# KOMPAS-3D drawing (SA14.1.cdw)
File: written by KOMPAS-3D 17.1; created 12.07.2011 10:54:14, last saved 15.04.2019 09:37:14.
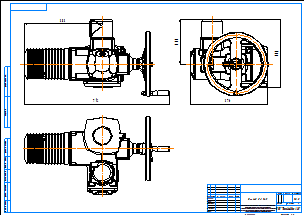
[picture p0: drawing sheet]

Title block, sheet 1: name: Привод SA 14.1; material: Внимание! Данный продукт является объектом авторского права ООО «Торговый Дом АДЛ». / Запрещается изменение, копирование, распространение / (в том числе путем копирования на другие сайты и ресурсы в Интернете) / или любое иное использование информации и объектов без предварительного / согласия правообладателя (ООО «Торговый Дом АДЛ»).; scale: 1:2,5; sheets: 1; organisation: ООО "Торговый дом АДЛ"; sheet format: A2; stored path: \\adlc.lan\data\АДЛ_ПКД\3D-модели\Поставщики\Сервоприводы AUMA\Электроприводы серии SA\KOMPAS 2D\Привод SA 14.1.cdw

Views: Проекционный вид 2, Проекционный вид 4, Проекционный вид 6
Dimensions and other numbers on the sheet: 220; 334; 376; 712; 383; 1:2,5; 1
